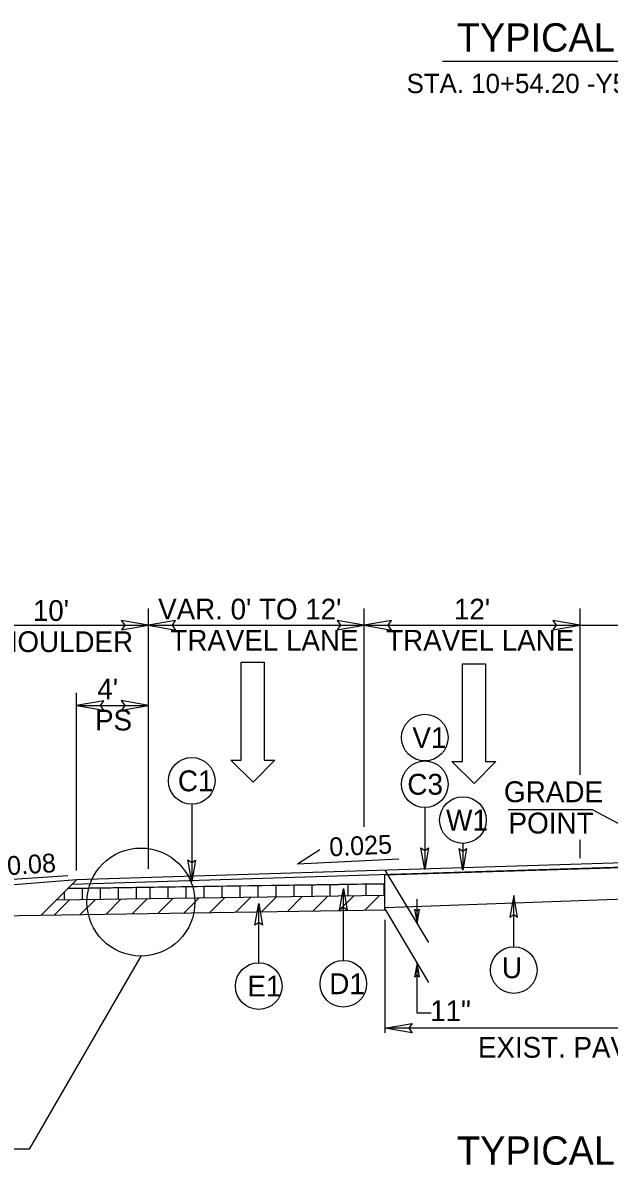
# Model space of a CAD drawing. Extents: x 2176156 to 2177167, y 76401 to 76644.
# Drawn here: x 2176760.2 to 2176792.8, y 76511.9 to 76575.4 of the extents above; entities that cross this region are included whole.
import ezdxf

# ---------------------------------------------------------------- set-up
doc = ezdxf.new("R2010")
doc.units = 0
for name, color, linetype in [('Exist Building', 7, 'Continuous'), ('Exist Building Metal Canopy', 7, 'Continuous'), ('Exist Roads Curbs', 7, 'Continuous'), ('Exist Roads EOP Other', 7, 'Continuous'), ('Exist Roads Soil', 7, 'Continuous'), ('Exist Structure Minor Culvert Topo', 7, 'Continuous'), ('Exist Structure Minor Drop Inlet', 7, 'Continuous'), ('Exist Utilities Other Pole CELL', 7, 'Continuous'), ('Exist Vegetation Woods Line', 7, 'Continuous'), ('Model Boundary Lines Text', 7, 'Continuous'), ('Old_Level_1', 7, 'Continuous'), ('Old_Level_3', 7, 'Continuous'), ('Prop North Arrow NAD83 for Plan Sheets CELL', 7, 'Continuous'), ('Sheet Plan CELL', 7, 'Continuous')]:
    doc.layers.add(name, color=color, linetype=linetype)

msp = doc.modelspace()

# ---------------------------------------------------------------- linework, layer by layer
at = {"layer": 'Exist Building'}
for p, q in [((2176780.289, 76526.112), (2176780.289, 76528.063)), ((2176747.04, 76525.617), (2176780.289, 76526.112))]:
    msp.add_line(p, q, dxfattribs=at)
at = {"layer": 'Exist Roads Curbs'}
for p, q in [((2176797.146, 76528.839), (2176763.146, 76527.778)), ((2176796.478, 76528.568), (2176762.886, 76527.52))]:
    msp.add_line(p, q, dxfattribs=at)
at = {"layer": 'Exist Roads EOP Other'}
for p, q in [((2176796.426, 76528.816), (2176763.146, 76527.778)), ((2176763.146, 76527.778), (2176757.111, 76527.296)), ((2176763.146, 76527.778), (2176762.886, 76527.52))]:
    msp.add_line(p, q, dxfattribs=at)
for points in [[(2176773.445, 76527.464), (2176774.959, 76527.487), (2176776.433, 76527.509), (2176777.013, 76527.517), (2176777.705, 76527.527), (2176778.76, 76527.543), (2176780.289, 76527.566), (2176780.289, 76528.063), (2176796.478, 76528.568)], [(2176762.886, 76527.52), (2176762.668, 76527.304), (2176773.445, 76527.464)]]:
    msp.add_lwpolyline(points, dxfattribs=at)
at = {"layer": 'Exist Roads Soil'}
for p, q in [((2176763.146, 76527.778), (2176761.184, 76525.828)), ((2176780.289, 76527.566), (2176762.668, 76527.304)), ((2176780.289, 76526.918), (2176762.007, 76526.646))]:
    msp.add_line(p, q, dxfattribs=at)
at = {"layer": 'Exist Structure Minor Drop Inlet'}
for p, q in [((2176772.305, 76534.44), (2176772.305, 76539.872)), ((2176772.305, 76539.872), (2176773.585, 76539.872)), ((2176773.585, 76539.872), (2176773.585, 76534.44)), ((2176784.604, 76534.355), (2176784.604, 76539.787)), ((2176784.604, 76539.787), (2176785.885, 76539.787)), ((2176785.885, 76539.787), (2176785.885, 76534.355)), ((2176772.964, 76533.218), (2176771.723, 76534.44)), ((2176771.723, 76534.44), (2176772.305, 76534.44)), ((2176774.167, 76534.44), (2176772.964, 76533.218)), ((2176773.585, 76534.44), (2176774.167, 76534.44)), ((2176785.264, 76533.133), (2176784.022, 76534.355)), ((2176784.022, 76534.355), (2176784.604, 76534.355)), ((2176786.467, 76534.355), (2176785.264, 76533.133)), ((2176785.885, 76534.355), (2176786.467, 76534.355))]:
    msp.add_line(p, q, dxfattribs=at)
at = {"layer": 'Exist Utilities Other Pole CELL'}
for p, q in [((2176775.434, 76528.68), (2176776.674, 76529.475)), ((2176775.434, 76528.68), (2176781.061, 76528.942)), ((2176757.906, 76527.71), (2176762.652, 76528.024))]:
    msp.add_line(p, q, dxfattribs=at)
at = {"layer": 'Model Boundary Lines Text'}
for p, q in [((2176783.485, 76573.271), (2176810.807, 76573.271)), ((2176775.242, 76526.843), (2176775.242, 76527.491)), ((2176776.242, 76526.858), (2176776.242, 76527.506)), ((2176777.242, 76526.873), (2176777.242, 76527.521)), ((2176778.242, 76526.888), (2176778.242, 76527.535)), ((2176779.242, 76526.903), (2176779.242, 76527.55)), ((2176780.242, 76526.918), (2176780.242, 76527.565)), ((2176762.469, 76526.653), (2176762.475, 76527.112)), ((2176763.469, 76526.668), (2176763.469, 76527.316)), ((2176764.469, 76526.683), (2176764.469, 76527.33)), ((2176765.469, 76526.698), (2176765.469, 76527.345)), ((2176766.469, 76526.713), (2176766.469, 76527.36)), ((2176767.242, 76526.724), (2176767.242, 76527.372)), ((2176768.242, 76526.739), (2176768.242, 76527.387)), ((2176769.242, 76526.754), (2176769.242, 76527.401)), ((2176770.242, 76526.769), (2176770.242, 76527.416)), ((2176771.242, 76526.784), (2176771.242, 76527.431)), ((2176772.242, 76526.799), (2176772.242, 76527.446)), ((2176773.242, 76526.813), (2176773.242, 76527.461)), ((2176774.242, 76526.828), (2176774.242, 76527.476)), ((2176776.302, 76526.053), (2176777.121, 76526.871)), ((2176777.738, 76526.074), (2176778.556, 76526.893)), ((2176779.173, 76526.095), (2176779.992, 76526.914)), ((2176761.916, 76525.839), (2176762.734, 76526.657)), ((2176763.351, 76525.86), (2176764.17, 76526.678)), ((2176764.787, 76525.881), (2176765.605, 76526.7)), ((2176766.253, 76525.903), (2176767.072, 76526.722)), ((2176767.689, 76525.924), (2176768.507, 76526.743)), ((2176769.124, 76525.946), (2176769.943, 76526.764)), ((2176770.56, 76525.967), (2176771.378, 76526.786)), ((2176771.995, 76525.989), (2176772.814, 76526.807)), ((2176773.431, 76526.01), (2176774.25, 76526.828)), ((2176774.867, 76526.031), (2176775.685, 76526.85))]:
    msp.add_line(p, q, dxfattribs=at)
at = {"layer": 'Old_Level_1'}
for points in [[(2176765.636, 76541.672), (2176767.146, 76541.932), (2176765.628, 76542.2), (2176765.821, 76541.932)], [(2176768.655, 76542.192), (2176767.146, 76541.932), (2176768.664, 76541.663), (2176768.471, 76541.932)], [(2176777.636, 76541.672), (2176779.146, 76541.932), (2176777.628, 76542.2), (2176777.821, 76541.932)], [(2176780.655, 76542.192), (2176779.146, 76541.932), (2176780.664, 76541.663), (2176780.471, 76541.932)], [(2176789.636, 76541.672), (2176791.146, 76541.932), (2176789.628, 76542.2), (2176789.821, 76541.932)], [(2176764.655, 76537.731), (2176763.146, 76537.471), (2176764.664, 76537.203), (2176764.471, 76537.471)], [(2176765.636, 76537.211), (2176767.146, 76537.471), (2176765.628, 76537.74), (2176765.821, 76537.471)], [(2176781.945, 76526.135), (2176782.077, 76525.38), (2176782.209, 76526.14), (2176782.075, 76526.043)], [(2176782.209, 76522.401), (2176782.077, 76523.156), (2176781.945, 76522.397), (2176782.079, 76522.493)], [(2176781.798, 76519.28), (2176780.289, 76519.54), (2176781.807, 76519.808), (2176781.614, 76519.54)]]:
    msp.add_lwpolyline(points, close=True, dxfattribs=at)
at = {"layer": 'Old_Level_3'}
for p, q in [((2176767.146, 76528.395), (2176767.146, 76542.859)), ((2176779.146, 76530.73), (2176779.146, 76542.859)), ((2176791.146, 76533.608), (2176791.146, 76542.859)), ((2176729.146, 76541.932), (2176797.172, 76541.932)), ((2176763.146, 76528.296), (2176763.146, 76538.181)), ((2176763.146, 76537.471), (2176767.146, 76537.471)), ((2176791.146, 76528.982), (2176791.146, 76530.003)), ((2176780.289, 76528.313), (2176782.714, 76524.305)), ((2176782.077, 76525.38), (2176782.077, 76526.709)), ((2176780.289, 76526.175), (2176782.714, 76522.081)), ((2176780.289, 76525.567), (2176780.289, 76519.286)), ((2176782.077, 76520.38), (2176782.077, 76523.156)), ((2176782.857, 76520.38), (2176782.077, 76520.38)), ((2176804.068, 76519.54), (2176780.289, 76519.54))]:
    msp.add_line(p, q, dxfattribs=at)
msp.add_lwpolyline([(2176766.722, 76523.55), (2176760.502, 76512.811), (2176758.848, 76512.812)], dxfattribs=at)
msp.add_circle((2176766.722, 76526.55), 3, dxfattribs=at)
at = {"layer": 'Prop North Arrow NAD83 for Plan Sheets CELL'}
for p, q in [((2176769.547, 76531.987), (2176769.547, 76527.684)), ((2176782.511, 76531.796), (2176782.511, 76528.355)), ((2176787.15, 76531.691), (2176791.82, 76531.691)), ((2176791.82, 76531.691), (2176797.146, 76528.839)), ((2176784.63, 76529.806), (2176784.63, 76528.323)), ((2176777.98, 76523.306), (2176777.98, 76527.306)), ((2176787.46, 76524.066), (2176787.46, 76526.908)), ((2176773.273, 76523.177), (2176773.273, 76526.473))]:
    msp.add_line(p, q, dxfattribs=at)
for points in [[(2176782.718, 76529.555), (2176782.511, 76528.355), (2176782.298, 76529.562), (2176782.511, 76529.408)], [(2176784.837, 76529.523), (2176784.63, 76528.323), (2176784.417, 76529.53), (2176784.63, 76529.377)], [(2176769.754, 76528.884), (2176769.547, 76527.684), (2176769.334, 76528.891), (2176769.547, 76528.738)], [(2176777.773, 76526.106), (2176777.98, 76527.306), (2176778.193, 76526.1), (2176777.98, 76526.253)], [(2176787.667, 76525.708), (2176787.46, 76526.908), (2176787.247, 76525.702), (2176787.46, 76525.855)], [(2176773.066, 76525.273), (2176773.273, 76526.473), (2176773.486, 76525.266), (2176773.273, 76525.42)]]:
    msp.add_lwpolyline(points, close=True, dxfattribs=at)
for centre in [(2176782.511, 76535.684), (2176769.547, 76533.283), (2176782.511, 76533.092), (2176784.63, 76531.102), (2176787.46, 76522.77), (2176773.273, 76521.881), (2176777.98, 76522.01)]:
    msp.add_circle(centre, 1.296, dxfattribs=at)
at = {"layer": 'Sheet Plan CELL'}
msp.add_line((2176780.289, 76526.248), (2176797.146, 76526.859), dxfattribs=at)

# ---------------------------------------------------------------- texts
at = {"layer": 'Exist Building Metal Canopy'}
for s, p in [('TYPICAL SECTION NO.  8', (2176784.288, 76573.8)), ('TYPICAL SECTION NO.  9', (2176784.299, 76511.952))]:
    msp.add_text(s, height=1.5766, rotation=0.00002, dxfattribs=at).set_placement(p)
at = {"layer": 'Exist Structure Minor Culvert Topo'}
for s, height, p in [("VAR. 0' TO 12'", 1.15334, (2176767.683, 76542.248)), ("12'", 1.1533, (2176784.132, 76542.248)), ("10' ", 1.1533, (2176760.715, 76542.169)), ('SHOULDER', 1.1533, (2176757.714, 76540.439)), ('TRAVEL LANE', 1.15334, (2176768.363, 76540.518)), ('TRAVEL LANE', 1.15334, (2176780.363, 76540.518)), ("4' ", 1.1533, (2176764.302, 76537.813)), ('PS', 1.1533, (2176764.172, 76536.083)), ("EXIST. PAVEMENT 21'", 1.15334, (2176785.466, 76517.899))]:
    msp.add_text(s, height=height, dxfattribs=at).set_placement(p)
at = {"layer": 'Exist Utilities Other Pole CELL'}
for s, rotation, p in [('0.025', 2.6676, (2176777.22, 76529.085)), ('0.08', 3.78012, (2176759.316, 76528.04))]:
    msp.add_text(s, height=1.0429, rotation=rotation, dxfattribs=at).set_placement(p)
at = {"layer": 'Exist Vegetation Woods Line'}
msp.add_text('STA. 10+54.20 -Y5- TO STA. 12+06.83 -Y5-', height=1.0742, dxfattribs=at).set_placement((2176781.498, 76571.497))
at = {"layer": 'Prop North Arrow NAD83 for Plan Sheets CELL'}
for s, rotation, p in [('V1', 0.00026, (2176781.818, 76535.104)), ('C1', 0.00026, (2176768.778, 76532.703)), ('C3', 0.00026, (2176781.539, 76532.512)), ('GRADE', 359.99985, (2176786.91, 76532.096)), ('W1', 0.00026, (2176783.693, 76530.522)), ('POINT', 359.99985, (2176787.163, 76530.356)), ('U', 359.99974, (2176786.797, 76522.316)), ('E1', 0.00026, (2176772.644, 76521.301)), ('D1', 0.00026, (2176777.195, 76521.43))]:
    msp.add_text(s, height=1.16, rotation=rotation, dxfattribs=at).set_placement(p)
msp.add_text('11"', height=1.1533, dxfattribs=at).set_placement((2176782.809, 76519.93))

doc.saveas('drawing.dxf')
